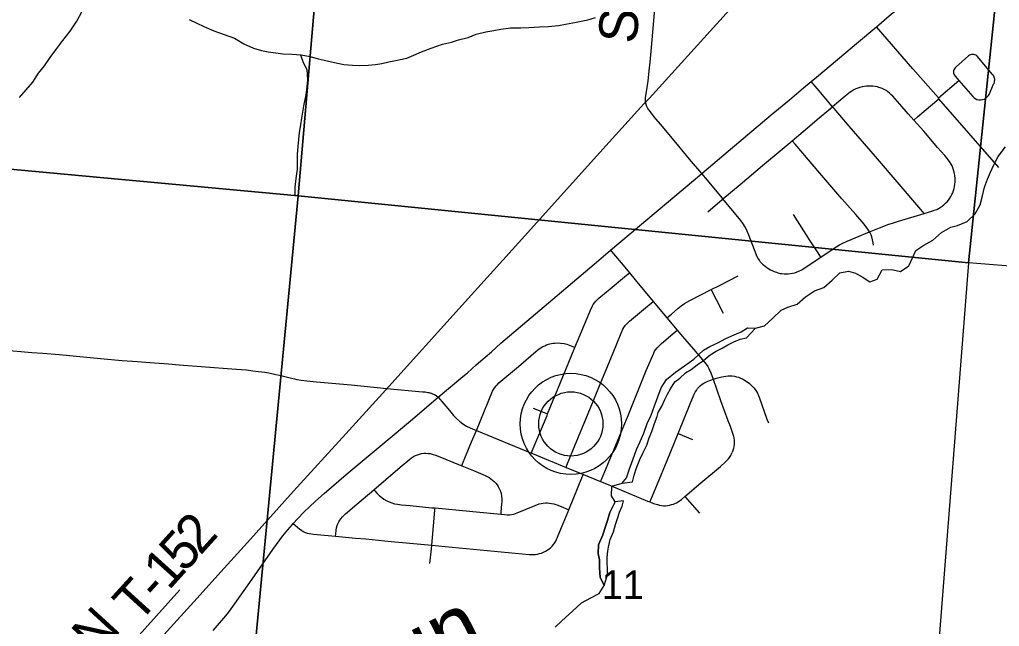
# Model space of a CAD drawing. Extents: x 0 to 1134, y 0 to 440.
# Drawn here: x 287.26 to 330.48, y 86.55 to 113.31 of the extents above; entities that cross this region are included whole.
import ezdxf

# ---------------------------------------------------------------- set-up
doc = ezdxf.new("R2010")
doc.units = 0
for name, color, linetype in [('GM_X_County_Road', 7, 'Continuous'), ('GM_X_County_Text', 7, 'Continuous'), ('GM_X_Minor_Lake', 7, 'Continuous'), ('GM_X_Minor_River', 7, 'Continuous'), ('GM_X_Minor_River_Text', 7, 'Continuous'), ('GM_X_Rail_Line', 7, 'Continuous'), ('GM_X_Section', 7, 'Continuous'), ('GM_X_Section_Text', 7, 'Continuous'), ('GM_X_Township_Road', 7, 'Continuous'), ('GM_X_Township_Road_Text', 7, 'Continuous'), ('GM_X_Unincorporated', 7, 'Continuous'), ('GM_X_Unincorporated_Location', 7, 'Continuous')]:
    doc.layers.add(name, color=color, linetype=linetype)

msp = doc.modelspace()

# ---------------------------------------------------------------- linework, layer by layer
at = {"layer": 'GM_X_County_Road'}
for points in [[(325.055, 112.998), (325.618, 113.472), (326.971, 114.613), (328.319, 115.759), (328.905, 116.25), (329.802, 116.992), (330.713, 117.752)], [(322.178, 110.583), (322.41, 110.776), (324.263, 112.334), (324.978, 112.932), (325.055, 112.998)], [(317.349, 106.525), (317.55, 106.694), (318.133, 107.182), (320.413, 109.107), (321.218, 109.773), (321.838, 110.299), (322.178, 110.583)], [(313.327, 103.139), (315.801, 105.221), (317.349, 106.525)], [(305.722, 96.656), (306.817, 97.571), (307.013, 97.739), (307.401, 98.082), (307.793, 98.418), (308.073, 98.667), (308.492, 99.041), (310.403, 100.666), (312.601, 102.529), (313.327, 103.139)], [(286.494, 98.743), (287.802, 98.636), (288.291, 98.601), (289.008, 98.538), (289.766, 98.473), (290.826, 98.373), (291.784, 98.282), (292.461, 98.232), (293.003, 98.192), (293.823, 98.129), (294.303, 98.092), (296.626, 97.912), (297.04, 97.879), (297.27, 97.859), (297.555, 97.829), (297.802, 97.799), (297.949, 97.779), (298.075, 97.759), (298.256, 97.728), (298.569, 97.663), (298.72, 97.631), (299.254, 97.492), (299.383, 97.467), (299.484, 97.447), (299.675, 97.415), (299.933, 97.383), (300.354, 97.333), (301.88, 97.198), (303.457, 97.047), (305.036, 96.901), (305.143, 96.889), (305.205, 96.882), (305.273, 96.871), (305.307, 96.864), (305.337, 96.857), (305.367, 96.847), (305.418, 96.831), (305.475, 96.81), (305.561, 96.777), (305.634, 96.735), (305.722, 96.656)], [(299.334, 91.09), (299.535, 91.304), (299.799, 91.587), (300.043, 91.826), (300.312, 92.074), (300.693, 92.413), (301.67, 93.25), (303.43, 94.72), (304.503, 95.615), (305.722, 96.656)], [(295.801, 86.374), (296.27, 86.91), (296.431, 87.109), (296.599, 87.332), (296.743, 87.525), (297.415, 88.48), (298.432, 89.947), (298.874, 90.545), (299.091, 90.814), (299.291, 91.044), (299.334, 91.09)]]:
    msp.add_lwpolyline(points, dxfattribs=at)
at = {"layer": 'GM_X_Minor_Lake'}
for points in [[(313.836, 92.87), (314.029, 93.107), (314.158, 93.504), (314.31, 93.899), (314.475, 94.352), (314.627, 94.703), (314.79, 95.076), (314.943, 95.495), (315.117, 95.867), (315.27, 96.275), (315.411, 96.682), (315.552, 97.067), (315.794, 97.439), (316.184, 97.764), (316.584, 98.043), (316.996, 98.334), (317.42, 98.727), (317.706, 98.894), (318.082, 99.071), (318.379, 99.238), (318.676, 99.359), (319.086, 99.547), (319.372, 99.714), (319.723, 99.699)], [(313.836, 92.87), (314.287, 92.922), (314.37, 93.217), (314.476, 93.545), (314.617, 93.918), (314.756, 94.19), (314.931, 94.551), (315.026, 94.868), (315.154, 95.151), (315.272, 95.502), (315.377, 95.808), (315.425, 95.989), (315.587, 96.26), (315.727, 96.554), (315.832, 96.791), (315.971, 97.028), (316.167, 97.332), (316.385, 97.5), (316.626, 97.736), (316.877, 97.881), (317.14, 98.082), (317.426, 98.283), (317.713, 98.53), (317.987, 98.686), (318.249, 98.819), (318.501, 98.964), (318.763, 99.097), (319.048, 99.218), (319.321, 99.283), (319.723, 99.699)], [(313.04, 88.356), (313.193, 88.82), (313.185, 89.071), (313.177, 89.366), (313.18, 89.594), (313.206, 89.866), (313.231, 90.048), (313.315, 90.388), (313.455, 90.727), (313.55, 91.044), (313.632, 91.316), (313.726, 91.588), (313.832, 91.859), (313.891, 92.086), (313.532, 92.04)], [(313.532, 92.04), (313.295, 91.57), (313.189, 91.219), (313.083, 90.913), (312.988, 90.585), (312.802, 90.155), (312.785, 89.769), (312.839, 89.484), (312.845, 89.12), (312.875, 88.722), (313.04, 88.356)]]:
    msp.add_lwpolyline(points, dxfattribs=at)
at = {"layer": 'GM_X_Minor_River'}
for points in [[(287.26, 109.871), (287.548, 110.22), (287.847, 110.546), (288.101, 110.952), (288.355, 111.278), (288.609, 111.639), (288.862, 111.977), (289.162, 112.394), (289.496, 112.799), (289.785, 113.239), (290.006, 113.657)], [(294.741, 113.315), (295.079, 113.152), (295.384, 113.011), (295.823, 112.813), (296.286, 112.659)], [(296.286, 112.659), (296.738, 112.495), (297.155, 112.251), (297.583, 112.053), (297.933, 111.957), (298.227, 111.897), (298.567, 111.847), (298.873, 111.809), (299.269, 111.793), (299.677, 111.754), (300.073, 111.681), (300.423, 111.586), (300.83, 111.501), (301.147, 111.418), (301.565, 111.333), (301.951, 111.306), (302.268, 111.291), (302.642, 111.309), (302.96, 111.328), (303.244, 111.381), (303.551, 111.445), (303.983, 111.531), (304.347, 111.618), (304.643, 111.75), (304.985, 111.894), (305.407, 112.059), (305.908, 112.224), (306.306, 112.321), (306.613, 112.42), (307.046, 112.528), (307.399, 112.672), (307.831, 112.769), (308.172, 112.833), (308.49, 112.886), (308.91, 112.949), (309.364, 112.955), (309.727, 112.962), (310.192, 112.99), (310.589, 113.008), (311.032, 113.048), (311.339, 113.112), (311.669, 113.177), (311.953, 113.23), (312.317, 113.305), (312.669, 113.403)], [(299.65, 111.757), (299.775, 111.423), (299.93, 111.115), (299.958, 110.66), (299.932, 110.342), (299.882, 110.001), (299.798, 109.582), (299.699, 108.969), (299.65, 108.674), (299.589, 108.334), (299.563, 108.027), (299.537, 107.732), (299.498, 107.369), (299.506, 107.073), (299.501, 106.721), (299.44, 106.301), (299.401, 105.926), (299.408, 105.551)], [(327.538, 103.581), (327.928, 103.929), (328.328, 104.151), (328.624, 104.227), (329.057, 104.404), (329.401, 104.752), (329.633, 105.147), (329.728, 105.544), (329.824, 105.918), (329.953, 106.28), (330.081, 106.585), (330.233, 106.902), (330.419, 107.274), (330.753, 107.702)], [(310.886, 86.518), (311.184, 86.799), (311.654, 87.225), (312.044, 87.595), (312.455, 87.818), (312.82, 87.995), (313.04, 88.356), (312.875, 88.722), (312.845, 89.12), (312.839, 89.484), (312.785, 89.769), (312.802, 90.155), (312.988, 90.585), (313.083, 90.913), (313.189, 91.219), (313.295, 91.57), (313.532, 92.04), (313.372, 92.308), (313.378, 92.729), (313.836, 92.87), (314.029, 93.107), (314.158, 93.504), (314.31, 93.899), (314.475, 94.352), (314.627, 94.703), (314.79, 95.076), (314.943, 95.495), (315.117, 95.867), (315.27, 96.275), (315.411, 96.682), (315.552, 97.067), (315.794, 97.439), (316.184, 97.764), (316.584, 98.043), (316.996, 98.334), (317.42, 98.727), (317.706, 98.894), (318.082, 99.071), (318.379, 99.238), (318.676, 99.359), (319.086, 99.547), (319.372, 99.714), (319.723, 99.699), (320.11, 99.808), (320.477, 100.144), (320.855, 100.503), (321.152, 100.625), (321.55, 100.756), (321.929, 101.093), (322.317, 101.349), (322.727, 101.503), (323.106, 101.828), (323.438, 102.143), (323.825, 102.218), (324.13, 102.134), (324.423, 101.971), (324.76, 101.74), (325.079, 101.872), (325.311, 102.279), (325.731, 102.285), (326.115, 102.201), (326.481, 102.458), (326.656, 102.831), (326.784, 103.136), (327.15, 103.37), (327.538, 103.581)]]:
    msp.add_lwpolyline(points, dxfattribs=at)
at = {"layer": 'GM_X_Rail_Line'}
msp.add_lwpolyline([(284.245, 75.831), (290.211, 82.409), (290.677, 82.925), (292.011, 84.405), (294.939, 87.635), (296.278, 89.117), (297.308, 90.247), (299.344, 92.509), (301.654, 95.046), (303.413, 96.991), (306.782, 100.725), (309.68, 103.924), (312.58, 107.136), (314.795, 109.591), (315.038, 109.843), (321.8, 117.334), (332.122, 128.732)], dxfattribs=at)
at = {"layer": 'GM_X_Section'}
for points in [[(273.637, 137.644), (302.061, 134.852), (299.553, 105.536), (270.808, 108.206)], [(331.546, 132.249), (332.181, 132.182), (329.111, 102.58), (299.553, 105.536), (302.061, 134.852)], [(332.181, 132.182), (361.662, 129.318), (362.32, 129.251), (359.621, 100.142), (329.111, 102.58)], [(270.808, 108.206), (299.553, 105.536), (296.601, 74.807), (267.778, 77.468)], [(329.111, 102.58), (326.718, 71.959), (296.601, 74.807), (299.553, 105.536)]]:
    msp.add_lwpolyline(points, close=True, dxfattribs=at)
at = {"layer": 'GM_X_Township_Road'}
for p, q in [((327.81, 109.825), (327.784, 109.855)), ((330.448, 106.787), (327.81, 109.825)), ((315.206, 100.882), (315.812, 100.156)), ((315.812, 100.156), (316.264, 99.614)), ((307.407, 95.192), (309.833, 94.193)), ((311.362, 93.565), (312.127, 93.25)), ((312.127, 93.25), (312.883, 92.94))]:
    msp.add_line(p, q, dxfattribs=at)
for points in [[(314.966, 110.506), (314.978, 110.598), (315.03, 111.059), (315.068, 111.428), (315.127, 112.077), (315.322, 114.304), (315.427, 115.51), (315.505, 116.438), (315.667, 118.293), (315.815, 120.057), (316.128, 123.675), (316.245, 125.067), (316.419, 127.015), (316.712, 130.449), (316.872, 132.118), (316.98, 133.23), (317.004, 133.529)], [(327.784, 109.855), (326.666, 111.143), (325.055, 112.998)], [(327.784, 109.855), (328.688, 110.62), (329.302, 109.923), (329.347, 109.877), (329.414, 109.829), (329.489, 109.795), (329.569, 109.776), (329.636, 109.771), (329.661, 109.772), (329.739, 109.783), (329.813, 109.809), (329.882, 109.848), (329.941, 109.9), (329.99, 109.961), (330.019, 110.015), (330.222, 110.458), (330.241, 110.5), (330.264, 110.58), (330.272, 110.663), (330.269, 110.69), (330.247, 110.769), (330.21, 110.843), (330.16, 110.909), (329.513, 111.678), (329.479, 111.712), (329.439, 111.74), (329.395, 111.76), (329.348, 111.773), (329.3, 111.777), (329.251, 111.773), (329.204, 111.76), (329.16, 111.74), (329.121, 111.712), (328.549, 111.217), (328.523, 111.189), (328.494, 111.148), (328.472, 111.102), (328.459, 111.053), (328.455, 111.003), (328.459, 110.953), (328.472, 110.904), (328.494, 110.859), (328.52, 110.82), (328.688, 110.62)], [(317.349, 106.525), (316.811, 107.163), (316.331, 107.733), (315.617, 108.593), (315.257, 109.021), (315.083, 109.241), (314.977, 109.397), (314.931, 109.482), (314.896, 109.572), (314.875, 109.667), (314.869, 109.764), (314.874, 109.859), (314.943, 110.322), (314.966, 110.506)], [(323.12, 109.464), (322.53, 110.171), (322.349, 110.383), (322.178, 110.583)], [(326.7, 108.879), (326.452, 109.158), (326.083, 109.584), (325.77, 109.936), (325.69, 110.012), (325.632, 110.067), (325.558, 110.126), (325.478, 110.18), (325.394, 110.227), (325.308, 110.268), (325.219, 110.303), (325.157, 110.324), (325.094, 110.341), (324.999, 110.362), (324.902, 110.375), (324.806, 110.381), (324.709, 110.381), (324.612, 110.375), (324.516, 110.363), (324.421, 110.345), (324.327, 110.32), (324.235, 110.289), (324.146, 110.253), (324.059, 110.21), (323.975, 110.161), (323.895, 110.106), (323.669, 109.929), (323.12, 109.464)], [(326.7, 108.879), (326.87, 109.024), (327.438, 109.508), (327.81, 109.825)], [(321.333, 107.967), (321.818, 108.374), (322.529, 108.976), (322.961, 109.332), (323.12, 109.464)], [(327.166, 104.767), (327.016, 104.942), (325.01, 107.269), (323.856, 108.609), (323.186, 109.385), (323.12, 109.464)], [(327.166, 104.767), (327.501, 104.866), (327.607, 104.902), (327.713, 104.942), (327.862, 105.026), (327.955, 105.086), (328.031, 105.147), (328.101, 105.212), (328.167, 105.281), (328.229, 105.353), (328.286, 105.43), (328.337, 105.51), (328.383, 105.593), (328.424, 105.679), (328.457, 105.769), (328.483, 105.86), (328.502, 105.954), (328.514, 106.048), (328.521, 106.142), (328.523, 106.244), (328.52, 106.331), (328.513, 106.409), (328.508, 106.455), (328.496, 106.515), (328.48, 106.586), (328.425, 106.769), (328.388, 106.857), (328.343, 106.942), (328.271, 107.056), (328.124, 107.25), (328.065, 107.323), (327.751, 107.676), (327.137, 108.386), (326.7, 108.879)], [(318.28, 105.409), (319.037, 106.034), (320.035, 106.875), (320.891, 107.595), (321.333, 107.967)], [(324.749, 103.948), (324.728, 103.986), (324.676, 104.063), (324.506, 104.285), (324.145, 104.713), (323.532, 105.415), (322.56, 106.547), (321.463, 107.816), (321.333, 107.967)], [(318.28, 105.409), (318.248, 105.448), (317.601, 106.234), (317.349, 106.525)], [(317.613, 104.833), (318.248, 105.381), (318.28, 105.409)], [(320.698, 102.145), (320.561, 102.19), (320.471, 102.228), (320.386, 102.268), (320.302, 102.313), (320.223, 102.364), (320.146, 102.42), (320.075, 102.482), (319.947, 102.621), (319.891, 102.699), (319.838, 102.778), (319.783, 102.872), (319.742, 102.965), (319.428, 103.81), (319.358, 103.979), (319.275, 104.143), (319.18, 104.299), (319.072, 104.446), (318.28, 105.409)], [(322.607, 102.839), (322.488, 103.02), (322.136, 103.556), (321.392, 104.711)], [(324.749, 103.948), (325.191, 104.133), (325.375, 104.206), (325.554, 104.274), (325.799, 104.355), (326.031, 104.428), (327.166, 104.767)], [(322.607, 102.839), (323.281, 103.285), (323.423, 103.374), (323.569, 103.457), (323.768, 103.543), (324.11, 103.681), (324.749, 103.948)], [(324.924, 103.37), (324.905, 103.461), (324.847, 103.735), (324.815, 103.822), (324.774, 103.905), (324.749, 103.948)], [(313.327, 103.139), (313.46, 102.981), (313.879, 102.482), (314.158, 102.144)], [(320.698, 102.145), (320.748, 102.131), (320.811, 102.119), (320.885, 102.109), (320.983, 102.1), (321.075, 102.1), (321.165, 102.1), (321.264, 102.11), (321.358, 102.125), (321.451, 102.149), (321.628, 102.216), (321.761, 102.282), (321.823, 102.319), (322.607, 102.839)], [(311.757, 98.854), (312.296, 100.151), (312.437, 100.494), (312.512, 100.664), (312.558, 100.745), (312.611, 100.821), (312.671, 100.892), (312.805, 101.021), (313.302, 101.439), (313.947, 101.97), (314.158, 102.144)], [(314.158, 102.144), (314.41, 101.836), (315.206, 100.882)], [(317.767, 101.402), (318.135, 101.591), (318.96, 102.012)], [(315.812, 100.156), (316.013, 100.328), (316.292, 100.569), (316.437, 100.682), (316.589, 100.785), (316.83, 100.92), (317.767, 101.402)], [(317.767, 101.402), (317.798, 101.341), (317.986, 100.975), (318.294, 100.36)], [(311.362, 93.565), (311.403, 93.663), (311.667, 94.306), (312.344, 95.945), (312.945, 97.414), (313.445, 98.622), (313.792, 99.49), (313.871, 99.659), (313.917, 99.74), (313.972, 99.815), (314.033, 99.886), (314.167, 100.016), (314.96, 100.67), (315.031, 100.731), (315.206, 100.882)], [(312.883, 92.94), (312.923, 93.036), (314.096, 95.854), (314.904, 97.833), (315.228, 98.603), (315.269, 98.685), (315.32, 98.763), (315.378, 98.835), (315.442, 98.902), (315.579, 99.028), (316.072, 99.45), (316.264, 99.614)], [(316.264, 99.614), (316.496, 99.336), (316.98, 98.771), (317.542, 98.11), (317.614, 98.015), (317.664, 97.925), (317.744, 97.729), (317.846, 97.448)], [(307.407, 95.192), (307.769, 96.065), (308.124, 96.924), (308.167, 97.006), (308.217, 97.084), (308.274, 97.158), (308.337, 97.226), (308.405, 97.289), (309.259, 98.007), (310.036, 98.673), (310.183, 98.787), (310.338, 98.889), (310.421, 98.931), (310.507, 98.965), (310.595, 98.995), (310.775, 99.036), (310.867, 99.049), (310.998, 99.054), (311.124, 99.048), (311.278, 99.027), (311.404, 98.994), (311.539, 98.943), (311.695, 98.88), (311.757, 98.854)], [(310.55, 95.92), (311.015, 97.062), (311.726, 98.778), (311.757, 98.854)], [(316.302, 95.058), (316.837, 96.37), (317.021, 96.798), (317.062, 96.881), (317.11, 96.961), (317.165, 97.037), (317.226, 97.107), (317.294, 97.171), (317.367, 97.228), (317.446, 97.278), (317.612, 97.362), (317.785, 97.43), (317.846, 97.448)], [(317.846, 97.448), (318.053, 97.512), (318.235, 97.559), (318.418, 97.593), (318.51, 97.601), (318.604, 97.602), (318.697, 97.596), (318.789, 97.584), (318.88, 97.564), (318.969, 97.536), (319.056, 97.503), (319.141, 97.464), (319.302, 97.372), (319.453, 97.262), (319.59, 97.137), (319.653, 97.068), (319.709, 96.994), (319.76, 96.915), (319.805, 96.834), (319.88, 96.663), (320.221, 95.697), (320.287, 95.523)], [(317.846, 97.448), (318.183, 96.511), (318.494, 95.633), (318.596, 95.375), (318.691, 95.115), (318.744, 94.94), (318.762, 94.851), (318.773, 94.762), (318.776, 94.671), (318.772, 94.581), (318.761, 94.491), (318.743, 94.393), (318.721, 94.309), (318.692, 94.218)], [(305.722, 96.656), (306.219, 96.079), (306.405, 95.853), (306.53, 95.719), (306.667, 95.596), (306.814, 95.486), (306.97, 95.389), (307.133, 95.305), (307.407, 95.192)], [(309.92, 96.175), (310.402, 95.98), (310.55, 95.92)], [(309.833, 94.193), (309.874, 94.291), (310.525, 95.858), (310.55, 95.92)], [(306.77, 93.639), (306.803, 93.717), (307.198, 94.691), (307.407, 95.192)], [(315.064, 92.04), (315.1, 92.129), (315.391, 92.834), (315.817, 93.868), (316.302, 95.058)], [(316.302, 95.058), (316.488, 94.979), (316.942, 94.787)], [(316.607, 92.283), (317.311, 92.88), (318.177, 93.607), (318.388, 93.795), (318.454, 93.862), (318.517, 93.932), (318.573, 94.007), (318.625, 94.086), (318.652, 94.136), (318.692, 94.218)], [(302.884, 92.577), (303.411, 93.023), (304.049, 93.567), (304.478, 93.928), (304.553, 93.986), (304.633, 94.038), (304.718, 94.083), (304.807, 94.119), (304.898, 94.148), (304.99, 94.169), (305.085, 94.184), (305.181, 94.189), (305.277, 94.183), (305.371, 94.17), (305.465, 94.15), (305.645, 94.092), (306.77, 93.639)], [(309.833, 94.193), (309.885, 94.171), (311.362, 93.565)], [(306.77, 93.639), (307.287, 93.426), (307.803, 93.209), (307.889, 93.167), (307.971, 93.118), (308.049, 93.064), (308.124, 93.006), (308.195, 92.942), (308.261, 92.873), (308.322, 92.799), (308.375, 92.72), (308.419, 92.634), (308.455, 92.545), (308.498, 92.427), (308.521, 92.3), (308.529, 92.164), (308.526, 92.066), (308.521, 91.941), (308.492, 91.598), (308.484, 91.502)], [(311.483, 91.697), (312.095, 93.172), (312.127, 93.25)], [(312.883, 92.94), (313.07, 92.863), (314.189, 92.403), (314.962, 92.08), (315.064, 92.04)], [(301.197, 90.528), (301.208, 90.622), (301.228, 90.798), (301.242, 90.893), (301.268, 90.997), (301.3, 91.078), (301.343, 91.165), (301.39, 91.237), (301.43, 91.294), (301.501, 91.378), (301.635, 91.512), (302.13, 91.939), (302.884, 92.577)], [(302.884, 92.577), (302.93, 92.526), (303.038, 92.405), (303.121, 92.326), (303.231, 92.231), (303.33, 92.161), (303.46, 92.088), (303.557, 92.041), (303.676, 91.996), (303.8, 91.961), (303.933, 91.936), (304.101, 91.917), (304.489, 91.879)], [(316.108, 91.947), (316.166, 91.97), (316.235, 92.002), (316.305, 92.044), (316.449, 92.149), (316.607, 92.283)], [(316.607, 92.283), (316.711, 92.162), (317.243, 91.543)], [(304.489, 91.879), (305.445, 91.787), (305.585, 91.774)], [(305.44, 90.133), (305.546, 91.324), (305.578, 91.697), (305.585, 91.774)], [(305.44, 90.133), (306.029, 90.08), (309.733, 89.728), (309.919, 89.722), (310.012, 89.728), (310.104, 89.742), (310.194, 89.762), (310.284, 89.788), (310.371, 89.821), (310.454, 89.863), (310.533, 89.909), (310.609, 89.963), (310.681, 90.022), (310.748, 90.086), (310.809, 90.156), (310.855, 90.227), (310.907, 90.314), (311.094, 90.738), (311.451, 91.617), (311.483, 91.697)], [(305.585, 91.774), (307.112, 91.635), (308.484, 91.502)], [(308.484, 91.502), (308.652, 91.485), (308.766, 91.478), (308.871, 91.477), (308.963, 91.486), (309.055, 91.503), (309.131, 91.526), (309.214, 91.558), (310.003, 91.884), (310.177, 91.95), (310.267, 91.974), (310.358, 91.99), (310.451, 91.999), (310.544, 91.999), (310.637, 91.992), (310.729, 91.978), (310.819, 91.958), (310.996, 91.899), (311.254, 91.792), (311.483, 91.697)], [(315.064, 92.04), (315.22, 91.977), (315.395, 91.92), (315.484, 91.898), (315.573, 91.882), (315.663, 91.872), (315.753, 91.871), (315.843, 91.879), (315.932, 91.895), (316.019, 91.92), (316.108, 91.947)], [(299.334, 91.09), (299.422, 91.015), (299.622, 90.845), (299.696, 90.788), (299.775, 90.738), (299.858, 90.697), (299.945, 90.666), (300.035, 90.644), (300.22, 90.617), (301.197, 90.528)], [(301.197, 90.528), (302.073, 90.449), (302.539, 90.407), (303.651, 90.3), (304.47, 90.221), (305.44, 90.133)], [(305.362, 89.329), (305.426, 89.971), (305.44, 90.133)], [(289.466, 82.84), (289.719, 83.118), (290.008, 83.436), (290.164, 83.614), (290.321, 83.787), (290.448, 83.925), (290.551, 84.033), (290.692, 84.175), (290.805, 84.296), (290.879, 84.376), (291.161, 84.679), (292.263, 85.865), (294.325, 88.16)]]:
    msp.add_lwpolyline(points, dxfattribs=at)
at = {"layer": 'GM_X_Unincorporated'}
for radius in [2.232, 1.415]:
    msp.add_circle((311.575, 95.481), radius, dxfattribs=at)
at = {"layer": 'GM_X_Unincorporated_Location'}
msp.add_line((311.575, 95.481), (311.575, 95.481), dxfattribs=at)

# ---------------------------------------------------------------- texts
at = {"layer": 'GM_X_County_Text'}
msp.add_text('CLARK COUNTY', height=5.68182, rotation=354.6384, dxfattribs=at).set_placement((250.939, 83.193))
at = {"layer": 'GM_X_Minor_River_Text'}
msp.add_text('Run', height=2.8407, rotation=26.9991, dxfattribs=at).set_placement((301.759, 82.51))
at = {"layer": 'GM_X_Section_Text'}
msp.add_text('11', height=1.2557, rotation=0, dxfattribs=at).set_placement((312.932, 87.761))
at = {"layer": 'GM_X_Township_Road_Text'}
for s, height, rotation, p in [('SNIDER', 1.7045, 84.874, (314.464, 112.217)), ('2', 1.705, 47.9772, (295.233, 89.651)), ('5', 1.705, 47.9772, (294.536, 88.878)), ('1', 1.705, 47.9772, (293.838, 88.104)), ('T', 1.705, 47.6962, (292.511, 86.64)), ('-', 1.705, 47.9785, (293.374, 87.588)), ('LN', 1.7045, 47.5276, (289.824, 84.255))]:
    msp.add_text(s, height=height, rotation=rotation, dxfattribs=at).set_placement(p)

doc.saveas('drawing.dxf')
